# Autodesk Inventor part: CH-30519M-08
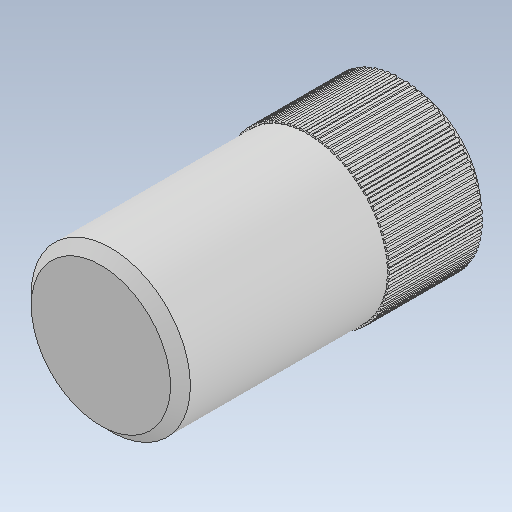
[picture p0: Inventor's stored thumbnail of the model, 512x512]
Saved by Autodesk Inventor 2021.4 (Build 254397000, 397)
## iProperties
Created: 2017-11
Part Number: CH-30519M-08
Material: Ogólny
Document SubType Name: Modeling
Designer: user
Density: 1 g/cm^3
Appearance: Domyślna
Author: user
Revision Number: ÈÎºÎ
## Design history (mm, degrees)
feature "ÕóÁÐ(Ô²ÖÜ)1"
node "Bryła1"
